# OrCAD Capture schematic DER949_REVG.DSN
size D; title: DER 949; rev: G
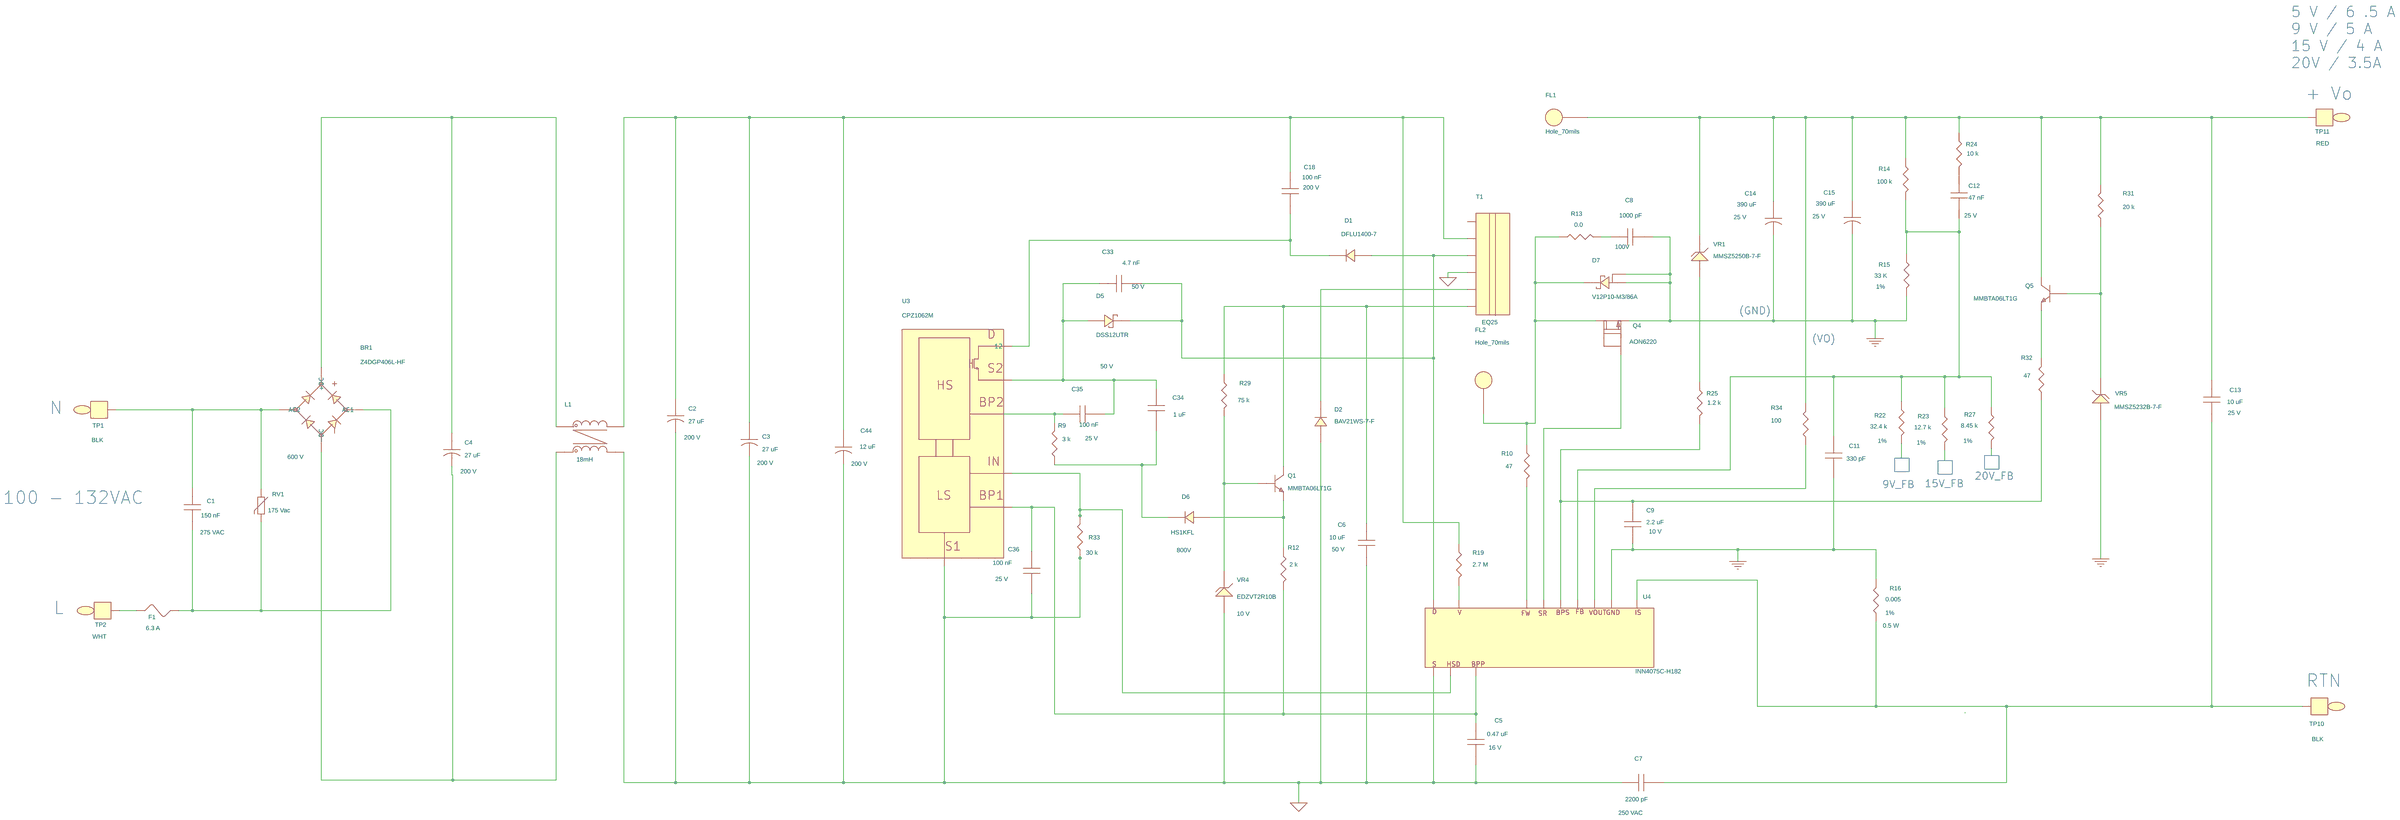
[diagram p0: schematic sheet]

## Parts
BR1  Z4DGP406L-HF  [pi_sm_d_z4d]
C1  150 nF  [pinpxcaprad475x255500040]
C2  27 uF  [pipolcapcyld400ls200040]
C3  27 uF  [pipolcapcyld400ls200040]
C4  27 uF  [pipolcapcyld400ls200040]
C5  0.47 uF  [pismc0603]
C6  10 uF  [pismc1206]
C7  2200 pF  [pinpcapraD9mmxLS10mm030]
C8  1000 pF  [pismc0603]
C9  2.2 uF  [pismc0603]
C11  330 pF  [pismc0603]
C12  47 nF  [pismc0603]
C13  10 uF  [pismc1206]
C14  390 uF  [pipolcapcyld400ls200040]
C15  390 uF  [pipolcapcyld400ls200040]
C18  100 nF  [pismc1206]
C33  4.7 nF  [pismc0603]
C34  1 uF  [pismc0805]
C35  100 nF  [pismc0603]
C36  100 nF  [pismc0603]
C44  12 uF  [pipolcapcyld3p5ls17ld40]
D1  DFLU1400-7  [pismddflr120012]
D2  BAV21WS-7-F  [pismsod323]
D5  DSS12UTR  [pi_sm_sod-123_12]
D6  HS1KFL  [pi_sm_sod-123_12]
D7  V12P10-M3/86A  [pi_sm_d_to-277a]
F1  6.3 A  [pi_v_ax_3-6x10_145ls200d030]
FL1  Hole_70mils  [pi_hole_70mil]
FL2  Hole_70mils  [pi_hole_70mil]
L1  18mH  [pi_CMC_18mH_Sumida]
Q1  MMBTA06LT1G  [pismsot23123_1]
Q4  AON6220  [pismpqfn5x6b]
Q5  MMBTA06LT1G  [pismsot23123_1]
R9  3 k  [pismr0603]
R10  47  [pismr0603]
R12  2 k  [pismr0603]
R13  0.0  [pismr0805]
R14  100 k  [pismr0603]
R15  33 K  [pismr0603]
R16  0.005  [pismr0805]
R19  2.7 M  [pismr1206]
R22  32.4 k  [pismr0603]
R23  12.7 k  [pismr0603]
R24  10 k  [pismr0603]
R25  1.2 k  [pismr0603]
R27  8.45 k  [pismr0603]
R29  75 k  [pismr0603]
R31  20 k  [pismr0603]
R32  47  [pismr0603]
R33  30 k  [pismr0603]
R34  100  [pismr0603]
RV1  175 Vac  [pi_disc_335x240ls200d040]
T1  EQ25  [pi_bobbin_eq-25_6p]
TP1  BLK  [pitpkeystone100x100]
TP2  WHT  [pitpkeystone100x100]
TP10  BLK  [pitpkeystone100x100]
TP11  RED  [pitpkeystone100x100]
U3  CPZ1062M  [PI_SM_MinSOP16A_1]
U4  INN4075C-H182  [pi_ic_insop_24d_IPC]
VR1  MMSZ5250B-7-F  [pi_sm_sod-123_12]
VR4  EDZVT2R10B  [pi_sm_d_ssmini2p]
VR5  MMSZ5232B-7-F  [pi_sm_sod-123_12]

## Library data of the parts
BR1 = DISCRETE_BRIDGE_+~~-: Disp_Voltage: 600 V; Part Number: 15-01613-00
C1 = CAP_NP: COMPGROUP: 1; Disp_Voltage: 275 VAC; Part Number: 20-00776-00; Voltage: 275 VAC
C2-C4 = CAP_POL: ALT_SYMBOLS: pipolcapclyd400x675ls200040h; Disp_Voltage: 200 V; FPLIST: pipolcapcyld400ls200040,pipolcapclyd400x675ls200040h; Part Number: 20-00610-00; Voltage: 200 V
C5 = CAP_NP: Disp_Voltage: 16 V; Part Number: 20-08990-00; Voltage: 16 V
C6 = CAP_NP: ALT_SYMBOLS: pismc1206_1; Disp_Voltage: 50 V; FPLIST: pismc1206,pismc1206_1; Part Number: 20-08995-00; Voltage: 50 V
C7 = CAP_NP: Disp_Voltage: 250 VAC; Part Number: 20-01656-00; Voltage: 250 VAC
C8 = CAP_NP: Disp_Voltage: 100V; Part Number: 20-09218-00; Voltage: 100V
C9 = CAP_NP: ALT_SYMBOLS: pismc0603_1; Disp_Voltage: 10 V; Part Number: 20-08740-00; Voltage: 10V
C11 = CAP_NP: Disp_Voltage: 50 V; Part Number: 20-08676-00; Voltage: 50 V
C12 = CAP_NP: Disp_Voltage: 25 V; Part Number: 20-08756-00; Voltage: 25 V
C13 = CAP_NP: Disp_Voltage: 25 V; Part Number: 20-01657-00; Voltage: 25 V
C14 C15 = CAP_POL: ALT_SYMBOLS: pipolcapclyd400x530ls200030h; COMPGROUP: 3; Disp_Voltage: 25 V; FPLIST: pipolcapcyld400ls200040,pipolcapclyd400x530ls200030h; Part Number: 20-08908-00; Voltage: 25 V
C18 = CAP_NP: Disp_Voltage: 200 V; Part Number: 20-00918-00; Voltage: 200 V
C33 = CAP_NP: Disp_Voltage: 50 V; Part Number: 20-09249-00; ROOM: 2; Voltage: 50 V
C34 = CAP_NP: Disp_Voltage: 50 V; Part Number: 20-00853-00; ROOM: 2; Voltage: 50 V
C35 C36 = CAP_NP: Disp_Voltage: 25 V; Part Number: 20-00528-00; ROOM: 2; Voltage: 25 V
C44 = CAP_POL: ALT_SYMBOLS: pipolcapcyld3p5ls17ld40H; Disp_Voltage: 200 V; FPLIST: pipolcapcyld3p5ls17ld40,pipolcapcyld3p5ls17ld40H; Part Number: 20-01600-00; Voltage: 200 V
D1 = DIODE: Part Number: 15-00910-00
D2 = DIODE: COMPGROUP: 1; Part Number: 15-00385-00
D5 = DIODE_SCHOTTKY: Part Number: 15-01670-00
D6 = DIODE: COMPGROUP: 2; Disp_Voltage: 800V; Part Number: 15-01686-00; ROOM: 2
D7 = DIODE_SCHOTTKY_TO-277A: Part Number: 15-00879-00
F1 = FUSE: ALT_SYMBOLS: pi_axial_3_6x10_145ls500d030; FPLIST: pi_v_ax_3-6x10_145ls200d030,pi_axial_3_6x10_145ls500d030; Part Number: 40-00028-00
FL1 FL2 = FlyingLead: Part Number: 35-00282-00
L1 = TORRID_4P_12_43a: ALT_SYMBOLS: pi_CMC_18mH_SumidaW,pi_CMC_18mH_Sumida_H,pi_CMC_18mH_SumidaSF; FPLIST: pi_CMC_18mH_Sumida,pi_CMC_18mH_SumidaW,pi_CMC_18mH_Sumida_H,pi_CMC_18mH_SumidaSF; Part Number: 30-00462-00
Q1 Q5 = NPN_BEC: Part Number: 55-00072-00; ROOM: 2
Q4 = FET_N_SGD_123_4_5678: Part Number: 50-00276-00
R9 = R: Part Number: 05-01699-00; ROOM: 2
R10 = R: ALT_SYMBOLS: pismr0603_1; Part Number: 05-01656-00
R12 = R: ALT_SYMBOLS: pismr0603_1; FPLIST: pismr0603,pismr0603_1; Part Number: 05-01695-00; ROOM: 2
R13 = R: ALT_SYMBOLS: pismr0805_1; FPLIST: pismr0805,pismr0805_1; Part Number: 05-03159-00
R14 = R: Disp_Tol: 1%; Part Number: 05-01174-00
R15 = R: Disp_Tol: 1%; Part Number: 05-06465-00
R16 = R: Disp_Power: 0.5 W; Disp_Tol: 1%; Part Number: 05-06481-00
R19 = R: Part Number: 05-01431-00
R22 = R: Disp_Tol: 1%; Part Number: 05-03233-00
R23 = R: Disp_Tol: 1%; Part Number: 05-03192-00
R24 = R: Part Number: 05-01712-00
R25 = R: Part Number: 05-01690-00
R27 = R: Disp_Tol: 1%; Part Number: 05-01167-00
R29 = R: Part Number: 05-01733-00; ROOM: 2
R31 = R: Part Number: 05-01719-00; ROOM: 2
R32 = R: ALT_SYMBOLS: pismr0603_1; FPLIST: pismr0603,pismr0603_1; Part Number: 05-01656-00; ROOM: 2
R33 = R: Part Number: 05-01723-00; ROOM: 2
R34 = R: Part Number: 05-01664-00; ROOM: 2
RV1 = VARISTOR: Part Number: 85-00025-00
T1 = BEQ25_6P: Part Number: 25-01136-00
TP1 TP10 = TESTPOINT: ALT_SYMBOLS: TP_TH_CR2_D1_1; FPLIST: pitpkeystone100x100,TP_TH_CR2_D1_1; Part Number: 35-00079-00
TP2 = TESTPOINT: Part Number: 35-00081-00
TP11 = TESTPOINT: Part Number: 35-00080-00
U3 = ClampZeroMinSOP16: Part Number: 10-01266-00; ROOM: 2
U4 = MinnoPriSecCZ: ALT_SYMBOLS: pi_ic_insop_24d,PI_IC_INSOP24B; FPLIST: pi_ic_insop_24d_IPC, pi_ic_insop_24d,PI_IC_INSOP24B; Part Number: 10-01261-01
VR1 = DIODE_ZENER: Part Number: 15-01093-00
VR4 = DIODE_ZENER: Disp_Voltage: 10 V; Part Number: 15-01591-00; ROOM: 2
VR5 = DIODE_ZENER: Part Number: 15-01082-00; ROOM: 2

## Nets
GND_POWER: C8.2 C9.1 C11.2 C14.2 C15.2 D7.1(A1) D7.2(A2) Q4.1(S) R15.2 R16.1 U4.2 VR5.2
GND_SIGNAL: C2.2 C3.2 C5.2 C6.2 C7.1 C36.2 C44.2 D2.2 L1.2 R33.1 T1.4 U3.3 U4.16 VR4.2
N11018979: C13.1 C14.1 C15.1 FL1.1 Q5.3(COLLECTOR) R14.1 R24.1 R31.1 R34.1 TP11.1 VR1.1
N11018991: C7.2 C13.2 R16.2 TP10.1 U4.1
N11019027: D7.3(Cathode) FL2.1 Q4.5(D) R10.1 R13.1
N11019153: C18.2 D1.1 U3.16(12)
N11019263: BR1.4(-DC) C4.2 L1.1
N11019397: BR1.3(AC2) C1.1 RV1.1 TP1.1
N11019401: C8.1 R13.2
N11019625: C2.1 C3.1 C18.1 C44.1 L1.3 R19.2 T1.2
N11019673: BR1.2(AC1) C1.2 F1.2 RV1.2
N11019681: BR1.1(+DC) C4.1 L1.4
N11019743: C11.1 C12.2 R14.2 R15.1 R22.1 R23.1 R27.1 U4.3
N11020753: C33.2 D1.2 D5.1 T1.3 U4.24
N11026403: F1.1 TP2.1
N11111738: C12.1 R24.2
N11114484: R25.1 VR1.2
N12705759: D2.1 T1.5
N12706342: C6.1 Q1.3(COLLECTOR) R29.1 T1.6
N12717194: R19.1 U4.13
N12732567: Q4.4(G) U4.5
N12733996: R10.2 U4.7
N12734050: C9.2 R25.2 R32.2 U4.4
N12734238: R34.2 U4.6
N12735016: C5.1 C36.1 R12.2 U3.8 U4.14
N12739704: Q1.1(BASE) R29.2 VR4.1
N12739734: D6.2 Q1.2(EMITTER) R12.1
N13029584: Q5.1(BASE) R31.2 VR5.1
N13029614: Q5.2(EMITTER) R32.1
N13041937: C33.1 C34.1 C35.2 D5.2 U3.10
N13042085: C35.1 R9.2 U3.9
N13042117: C34.2 D6.1 R9.1
N13042133: R33.2 U3.7 U4.15

Not connected (* = marked no-connect by the designer): Q4 2(S2) 3(S3) 6(D6) 7(D7) 8(D8); R22 2; R23 2; R27 2; T1 1; U3 1 2 4 5 6 11

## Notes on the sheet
- 5 V / 6 .5 A
  9 V / 5 A
  15 V / 4 A
  20V / 3.5A
- + Vo
- (GND)
- (VO)
- N
- 20V_FB
- 9V_FB
- 15V_FB
- 100 - 132VAC
- L
- RTN
